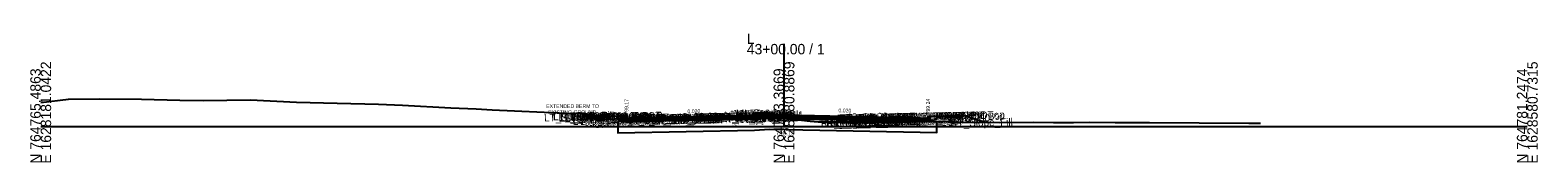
# Model space of a CAD drawing. Extents: x -26 to 4403, y -510 to 9556.
# Drawn here: x 2997.2 to 3402.8, y 2990.3 to 3025 of the extents above; entities that cross this region are included whole.
import ezdxf

# ---------------------------------------------------------------- set-up
doc = ezdxf.new("R2010")
doc.units = 0
for name, color, linetype in [('Default', 7, 'Continuous'), ('Exist Cross Section Cell', 7, 'Continuous'), ('Exist XS Center Line Elevation Label', 7, 'Continuous'), ('Exist XS Ground Line', 7, 'Continuous'), ('Prop CMT Conc Surface', 7, 'Continuous'), ('Prop CMT Concrete Structures', 7, 'Continuous'), ('Prop CMT Pvmt Course 1', 7, 'Continuous'), ('Prop CMT Pvmt Course 1 CG', 7, 'Continuous'), ('Prop CMT Pvmt Course 2', 7, 'Continuous'), ('Prop CMT Pvmt Course 3', 7, 'Continuous'), ('Prop CMT Pvmt Surface', 7, 'Continuous'), ('Prop CMT Pvmt Wedge Surface 1', 7, 'Continuous'), ('Prop CMT Pvmt Wedge Surface 2', 7, 'Continuous'), ('Prop CMT Pvmt Wedge Surface 3', 7, 'Continuous'), ('Prop CMT Slope Grass', 7, 'Continuous'), ('Prop CMT Subgrade Earthwork', 7, 'Continuous'), ('Prop CMT Undercut Boundary', 7, 'Continuous'), ('Prop XS Hydro Elevations', 7, 'Continuous'), ('Prop XS SE Text', 7, 'Continuous'), ('Prop XS Side Slope Text', 7, 'Continuous'), ('Scratch_Level_0', 7, 'Continuous')]:
    doc.layers.add(name, color=color, linetype=linetype)

msp = doc.modelspace()

# ---------------------------------------------------------------- linework, layer by layer
at = {"layer": 'Exist Cross Section Cell'}
for p, q in [((3200, 3000), (3200, 3022.2)), ((3000, 3000), (3200, 3000)), ((3200, 3000), (3400, 3000))]:
    msp.add_line(p, q, dxfattribs=at)
at = {"layer": 'Exist XS Ground Line'}
msp.add_lwpolyline([(3000, 3006.4), (3007.49, 3007.37), (3015.71, 3007.4), (3027.09, 3007.3), (3037.46, 3007.05), (3043.67, 3006.98), (3056.46, 3007.12), (3068.87, 3006.52), (3079.73, 3006.28), (3090.92, 3006.01), (3097.37, 3005.71), (3110.36, 3004.98), (3117.15, 3004.73), (3121.46, 3004.51), (3141.5, 3003.56), (3142.88, 3003.49), (3145.13, 3003.63), (3146.98, 3002.99), (3149.21, 3002.07), (3149.54, 3002.06), (3150, 3001.86), (3152.18, 3001.94), (3162.01, 3002.31), (3168.3, 3002.36), (3172.37, 3002.43), (3177, 3002.33), (3184.33, 3002.19), (3187.04, 3002.07), (3191.4, 3001.93), (3192.07, 3001.88), (3192.87, 3001.79), (3193.93, 3002.11), (3194.02, 3002.27), (3198.04, 3002.39), (3200, 3002.19), (3207.07, 3001.44), (3209.15, 3001.26), (3214.68, 3001.19), (3219.49, 3001.16), (3225.65, 3001.12), (3240.12, 3001.3), (3248.2, 3001.14), (3258.01, 3001.05), (3267.03, 3001.14), (3272.52, 3001.05), (3277.9, 3001.1), (3282.3, 3001.14), (3289.08, 3001.1), (3298.38, 3001.05), (3325.08, 3000.86), (3328.19, 3000.84)], dxfattribs=at)
at = {"layer": 'Prop CMT Conc Surface'}
for points in [[(3153.1, 3002.76), (3148.1, 3002.86)], [(3153.1, 3002.76), (3153.1, 3002.76)], [(3157.61, 3002.17), (3157.61, 3002.67), (3157.11, 3002.67)], [(3159.61, 3002.29), (3157.61, 3002.17)], [(3236.75, 3002.36), (3238.75, 3002.24)], [(3238.75, 3002.24), (3238.75, 3002.74), (3239.25, 3002.74)], [(3243.25, 3002.83), (3248.25, 3002.93)]]:
    msp.add_lwpolyline(points, dxfattribs=at)
at = {"layer": 'Prop CMT Concrete Structures'}
for points in [[(3148.1, 3002.53), (3148.1, 3002.86)], [(3148.1, 3002.86), (3153.1, 3002.76)], [(3153.1, 3002.43), (3148.1, 3002.53)], [(3153.1, 3002.76), (3153.1, 3002.76)], [(3159.61, 3002.29), (3157.61, 3002.17), (3157.61, 3002.67), (3157.11, 3002.67)], [(3157.11, 3002.67), (3157.11, 3001.66), (3159.61, 3001.71)], [(3159.61, 3001.71), (3159.61, 3002.29)], [(3196, 3003.18), (3195.99, 3003.35), (3195.24, 3003.6), (3194, 3003.62), (3192.76, 3003.36), (3192.01, 3003.11), (3192, 3002.94)], [(3192, 3002.94), (3196, 3003.18)], [(3236.75, 3002.36), (3238.75, 3002.24), (3238.75, 3002.74), (3239.25, 3002.74)], [(3239.25, 3002.74), (3239.25, 3001.73), (3236.75, 3001.78)], [(3236.75, 3001.78), (3236.75, 3002.36)], [(3248.25, 3002.93), (3243.25, 3002.83)], [(3243.25, 3002.83), (3243.25, 3002.5)], [(3243.25, 3002.5), (3248.25, 3002.6)], [(3248.25, 3002.6), (3248.25, 3002.93)]]:
    msp.add_lwpolyline(points, dxfattribs=at)
msp.add_lwpolyline([(3153.1, 3002.76), (3153.1, 3002.43), (3153.1, 3002.43)], close=True, dxfattribs=at)
at = {"layer": 'Prop CMT Pvmt Course 1'}
for points in [[(3192, 3002.94), (3159.61, 3002.29)], [(3159.61, 3002.04), (3192, 3002.69)], [(3159.61, 3002.29), (3159.61, 3002.04)], [(3175, 3002.35), (3192, 3002.69)], [(3192, 3002.94), (3196, 3003.18)], [(3192, 3002.69), (3192, 3002.94)], [(3192, 3002.69), (3192, 3002.94)], [(3196, 3002.93), (3192, 3002.69)], [(3196, 3003.18), (3196, 3002.93)], [(3196, 3003.18), (3236.75, 3002.36)], [(3196, 3002.93), (3196, 3003.18)], [(3236.75, 3002.11), (3196, 3002.93)], [(3225, 3002.35), (3196, 3002.93)], [(3236.75, 3002.36), (3236.75, 3002.11)]]:
    msp.add_lwpolyline(points, dxfattribs=at)
at = {"layer": 'Prop CMT Pvmt Course 1 CG'}
for points in [[(3159.61, 3001.71), (3156.61, 3001.65), (3156.27, 3001.31)], [(3156.27, 3001.31), (3159.61, 3001.37)], [(3159.61, 3001.37), (3159.61, 3001.71)], [(3236.75, 3001.78), (3239.75, 3001.72), (3240.09, 3001.38)], [(3236.75, 3001.45), (3236.75, 3001.78)], [(3240.09, 3001.38), (3236.75, 3001.45)]]:
    msp.add_lwpolyline(points, dxfattribs=at)
at = {"layer": 'Prop CMT Pvmt Course 2'}
for points in [[(3192, 3002.69), (3159.61, 3002.04)], [(3159.61, 3001.71), (3192, 3002.36)], [(3192, 3002.69), (3175, 3002.35)], [(3175, 3002.02), (3192, 3002.36)], [(3192, 3002.69), (3196, 3002.93)], [(3192, 3002.36), (3192, 3002.69)], [(3192, 3002.36), (3192, 3002.69)], [(3196, 3002.6), (3192, 3002.36)], [(3196, 3002.93), (3196, 3002.6)], [(3196, 3002.6), (3196, 3002.93)], [(3196, 3002.93), (3225, 3002.35)], [(3196, 3002.93), (3236.75, 3002.11)], [(3225, 3002.02), (3196, 3002.6)], [(3236.75, 3001.78), (3196, 3002.6)], [(3236.75, 3002.11), (3236.75, 3001.78)], [(3159.61, 3002.04), (3159.61, 3001.71)]]:
    msp.add_lwpolyline(points, dxfattribs=at)
at = {"layer": 'Prop CMT Pvmt Course 3'}
for points in [[(3192, 3002.36), (3159.61, 3001.71)], [(3192, 3002.36), (3175, 3002.02)], [(3192, 3002.36), (3196, 3002.6)], [(3192, 3002.02), (3192, 3002.36)], [(3192, 3002.02), (3192, 3002.36)], [(3196, 3002.26), (3192, 3002.02)], [(3196, 3002.6), (3196, 3002.26)], [(3196, 3002.6), (3225, 3002.02)], [(3196, 3002.26), (3196, 3002.6)], [(3196, 3002.6), (3236.75, 3001.78)], [(3225, 3001.68), (3196, 3002.26)], [(3236.75, 3001.45), (3196, 3002.26)], [(3159.61, 3001.37), (3192, 3002.02)], [(3159.61, 3001.71), (3159.61, 3001.37)], [(3175, 3001.68), (3192, 3002.02)], [(3236.75, 3001.78), (3236.75, 3001.45)]]:
    msp.add_lwpolyline(points, dxfattribs=at)
at = {"layer": 'Prop CMT Pvmt Surface'}
for points in [[(3192, 3002.94), (3159.61, 3002.29)], [(3192, 3002.94), (3196, 3003.18)], [(3196, 3003.18), (3236.75, 3002.36)]]:
    msp.add_lwpolyline(points, dxfattribs=at)
at = {"layer": 'Prop CMT Pvmt Wedge Surface 1'}
for points in [[(3192, 3002.69), (3159.61, 3002.04)], [(3159.61, 3002.04), (3159.61, 3002.29)], [(3192, 3002.69), (3175, 3002.35)], [(3192, 3002.94), (3192, 3002.69)], [(3196, 3003.18), (3196, 3002.93)], [(3196, 3002.93), (3225, 3002.35)], [(3196, 3002.93), (3236.75, 3002.11)], [(3236.75, 3002.11), (3236.75, 3002.36)]]:
    msp.add_lwpolyline(points, dxfattribs=at)
at = {"layer": 'Prop CMT Pvmt Wedge Surface 2'}
for points in [[(3192, 3002.69), (3159.61, 3002.04)], [(3159.61, 3002.04), (3159.61, 3002.29)], [(3192, 3002.94), (3192, 3002.69)], [(3196, 3003.18), (3196, 3002.93)], [(3236.75, 3002.11), (3236.75, 3002.36)]]:
    msp.add_lwpolyline(points, dxfattribs=at)
at = {"layer": 'Prop CMT Pvmt Wedge Surface 3'}
for points in [[(3159.61, 3001.71), (3159.61, 3002.29)], [(3192, 3002.94), (3192, 3002.36)], [(3196, 3003.18), (3196, 3002.6)], [(3236.75, 3001.78), (3236.75, 3002.36)]]:
    msp.add_lwpolyline(points, dxfattribs=at)
at = {"layer": 'Prop CMT Slope Grass'}
for points in [[(3147.59, 3002.86), (3147.27, 3002.87)], [(3157.11, 3002.67), (3147.59, 3002.86)], [(3239.25, 3002.74), (3248.25, 3002.92)], [(3248.25, 3002.92), (3248.75, 3002.93), (3254.3, 3001.08)]]:
    msp.add_lwpolyline(points, dxfattribs=at)
at = {"layer": 'Prop CMT Subgrade Earthwork'}
for points in [[(3159.61, 3001.37), (3156.27, 3001.31), (3154.87, 3002.72)], [(3192, 3002.02), (3196, 3002.26)], [(3196, 3002.26), (3236.75, 3001.45)], [(3196, 3002.26), (3225, 3001.68)], [(3236.75, 3001.45), (3240.09, 3001.38), (3241.5, 3002.79)], [(3192, 3002.02), (3159.61, 3001.37)]]:
    msp.add_lwpolyline(points, dxfattribs=at)
at = {"layer": 'Prop CMT Undercut Boundary'}
msp.add_lwpolyline([(3155.27, 3001.29), (3155.27, 2998.29), (3192.1, 2999.02), (3196.06, 2999.26), (3241.09, 2998.36), (3241.09, 3001.28), (3240.12, 3001.3), (3230.99, 3001.19), (3225.65, 3001.12), (3222.57, 3001.14), (3219.49, 3001.16), (3217.08, 3001.18), (3214.68, 3001.19), (3211.92, 3001.23), (3209.15, 3001.26), (3208.11, 3001.35), (3207.07, 3001.44), (3203.54, 3001.81), (3200.54, 3002.13), (3200.04, 3002.18), (3196, 3002.26), (3193.95, 3002.14), (3193.93, 3002.11), (3192.87, 3001.79), (3192.07, 3001.88), (3191.73, 3001.9), (3191.4, 3001.93), (3189.87, 3001.98)], close=True, dxfattribs=at)

# ---------------------------------------------------------------- texts
at = {"layer": 'Default'}
msp.add_text('-', height=0.0001, dxfattribs=at).set_placement((3000, 3000))
at = {"layer": 'Exist Cross Section Cell'}
for s, p in [('43+00.00 / 1', (3190, 3019.4)), ('L', (3190, 3022.2))]:
    msp.add_text(s, height=2.8, dxfattribs=at).set_placement(p)
for s, p in [('N 764765.4863', (3000, 2990)), ('E 1628181.0422', (3002.8, 2990)), ('N 764773.3669', (3200, 2990)), ('E 1628380.8869', (3202.8, 2990)), ('N 764781.2474', (3400, 2990)), ('E 1628580.7315', (3402.8, 2990))]:
    msp.add_text(s, height=2.8, rotation=90, dxfattribs=at).set_placement(p)
at = {"layer": 'Exist XS Center Line Elevation Label'}
msp.add_text('799.19', height=1.2, dxfattribs=at).set_placement((3197.78, 2997.59))
at = {"layer": 'Prop XS Hydro Elevations'}
for s, p in [('799.17', (3158.11, 3003.17)), ('799.24', (3239.25, 3003.24))]:
    msp.add_text(s, height=1, rotation=90, dxfattribs=at).set_placement(p)
at = {"layer": 'Prop XS SE Text'}
for rotation, p in [(1.1462, (3174.04, 3003.58)), (358.8542, (3214.65, 3003.81))]:
    msp.add_text('0.020', height=1, rotation=rotation, dxfattribs=at).set_placement(p)
at = {"layer": 'Prop XS Side Slope Text'}
for s, p in [('EXTENDED BERM TO', (3136.02, 3004.97)), ('EXISTING GROUND', (3136.53, 3003.34))]:
    msp.add_text(s, height=1, dxfattribs=at).set_placement(p)
msp.add_text('3:1', height=1, rotation=341.5651, dxfattribs=at).set_placement((3251.39, 3002.87))
at = {"layer": 'Scratch_Level_0'}
for s, p in [('LT_Sub_Trench_Out_DLT', (3135.46, 3001.33)), ('LT_CSLP_Pnt', (3137.78, 3001.67)), ('LT_Slope_Fill', (3137.96, 3001.62)), ('LT_SDWK_Out_Top', (3139.36, 3001.49)), ('LT_SDWK_Out_Bot', (3139.39, 3001.15)), ('43+00.00', (3140.66, 3001.69)), ('LT_SDWK_In_Top', (3140.98, 3001.52)), ('LT_SDWK_In_Bot', (3141.01, 3001.19)), ('LT_CG1_Shelf_Out', (3143.19, 3000.38)), ('LT_CG_Top_Face', (3144.89, 3001.42)), ('LT_CG_Top_BOC', (3145.42, 3001.44)), ('LT_CG_Bot_BOC', (3145.45, 3000.42)), ('LT_CG_Top_Gut', (3145.87, 3000.94)), ('LT_Sub_OEOP', (3146.41, 3000.11)), ('43+00.00', (3146.83, 3001.61)), ('LT_Sub_OEOT_CG', (3147.01, 3000.12)), ('LT_CG_Bot_IE', (3149.55, 3000.51)), ('LT_Sub_OEOT', (3149.71, 3000.18)), ('LT_PV2_OEOT', (3149.81, 3000.84)), ('LT_PV3_OEOT', (3149.81, 3000.51)), ('43+00.00', (3150.03, 3001.54)), ('LT_PV1_OEOT', (3150.37, 3001.11)), ('43+00.00', (3151.56, 3001.08)), ('LT_PV_Sub_Tie_Out', (3159.98, 3001.07)), ('LT_PV_EG_TestPt', (3161.43, 3001.1)), ('LT_PV_Sub_Tie_In', (3161.57, 3001.1)), ('LT_PV_OEEOP_EG', (3162.57, 3001.12)), ('LT_PV_IEEOP_EG', (3163.21, 3001.14)), ('LT_Sub_OEEOP', (3164.23, 3000.47)), ('LT_PV2_OEEOP', (3164.33, 3001.14)), ('LT_PV3_OEEOP', (3164.33, 3000.8)), ('LT_Sub_IEEOP', (3164.88, 3000.48)), ('LT_PV1_OEEOP', (3164.9, 3001.27)), ('LT_PV2_IEEOP', (3164.97, 3001.15)), ('LT_PV3_IEEOP', (3164.97, 3000.82)), ('LT_PV1_IEEOP', (3165.54, 3001.28)), ('43+00.00', (3171.12, 3001.52)), ('LT_PV2_PGL1', (3182.9, 3001.51)), ('LT_PV3_PGL1', (3182.9, 3001.17)), ('LT_Sub_PGL', (3183.14, 3000.84)), ('LT_PV2_PGL', (3183.23, 3001.51)), ('LT_PV3_PGL', (3183.23, 3001.18)), ('LT_PV4_PGL', (3183.23, 3000.85)), ('LT_PV1_PGL', (3183.8, 3001.77)), ('MI_Face In', (3183.92, 3001.94)), ('43+00.00', (3185.2, 3001.96)), ('43+00.00', (3185.23, 3001.98)), ('MI_Top In', (3185.63, 3002.21)), ('MI_Face Out', (3186.28, 3002.15)), ('43+00.00', (3186.56, 3002.35)), ('MI_Top Out', (3186.49, 3002.42)), ('RT_PV2_PGL1', (3186.86, 3001.75)), ('RT_PV3_PGL1', (3186.86, 3001.41)), ('MI_Crown', (3187.09, 3002.48)), ('RT_Sub_PGL', (3187.09, 3001.08)), ('RT_PV2_PGL', (3187.19, 3001.75)), ('RT_PV3_PGL', (3187.19, 3001.42)), ('RT_PV4_PGL', (3187.19, 3001.09)), ('MI_Bot Out', (3187.28, 3002)), ('RT_PV1_PGL', (3187.75, 3002.01)), ('43+00.00', (3188.93, 3002.29)), ('43+00.00', (3189.18, 3002.14)), ('RT_PV_Sub_Tie_Out', (3209.91, 2999.83)), ('RT_PV_EG_TestPt', (3211.38, 2999.85)), ('RT_PV_Sub_Tie_In', (3211.56, 2999.86)), ('RT_PV_OEEOP_EG', (3212.52, 2999.88)), ('RT_PV_IEEOP_EG', (3213.16, 2999.89)), ('RT_Sub_OEEOP', (3214.19, 3000.47)), ('RT_PV2_OEEOP', (3214.28, 3001.13)), ('RT_PV3_OEEOP', (3214.28, 3000.8)), ('RT_Sub_IEEOP', (3214.83, 3000.48)), ('RT_PV1_OEEOP', (3214.85, 3001.27)), ('RT_PV2_IEEOP', (3214.93, 3001.15)), ('RT_PV3_IEEOP', (3214.93, 3000.81)), ('RT_PV1_IEEOP', (3215.49, 3001.28)), ('43+00.00', (3216.77, 3001.49)), ('RT_Sub_Trench_Out_DLT', (3222.04, 3001.4)), ('RT_Sub_OEOT_CG', (3224.1, 3000.19)), ('RT_CG_Top_Face', (3225.99, 3001.49)), ('RT_CG1_Shelf_Out', (3226.28, 3000.45)), ('RT_CG_Bot_IE', (3226.64, 3000.58)), ('RT_Sub_OEOT', (3226.8, 3000.25)), ('RT_PV2_OEOT', (3226.9, 3000.92)), ('RT_PV3_OEOT', (3226.9, 3000.58)), ('RT_CG_Top_Gut', (3226.96, 3001.01)), ('RT_PV1_OEOT', (3227.46, 3001.18)), ('RT_CG_Top_BOC', (3227.51, 3001.51)), ('RT_CG_Bot_BOC', (3227.54, 3000.5)), ('RT_Sub_OEOP', (3230.18, 3000.18)), ('RT_SDWK_In_Top', (3231.08, 3001.59)), ('RT_SDWK_In_Bot', (3231.11, 3001.26)), ('43+00.00', (3232.12, 3001.61)), ('RT_SDWK_Out_Top', (3234.46, 3001.66)), ('RT_SDWK_Out_Bot', (3234.49, 3001.33)), ('43+00.00', (3234.66, 3001.65)), ('43+00.00', (3235.58, 3001.68)), ('RT_Shld_O', (3240.81, 3001.77)), ('43+00.00', (3241.46, 3001.8)), ('CSLP_Pnt', (3241.64, 3001.79)), ('43+00.00', (3244.22, 3001.04)), ('RT_Slope_Fill', (3244.79, 2999.89))]:
    msp.add_text(s, height=2, rotation=1.1458, dxfattribs=at).set_placement(p)

doc.saveas('drawing.dxf')
